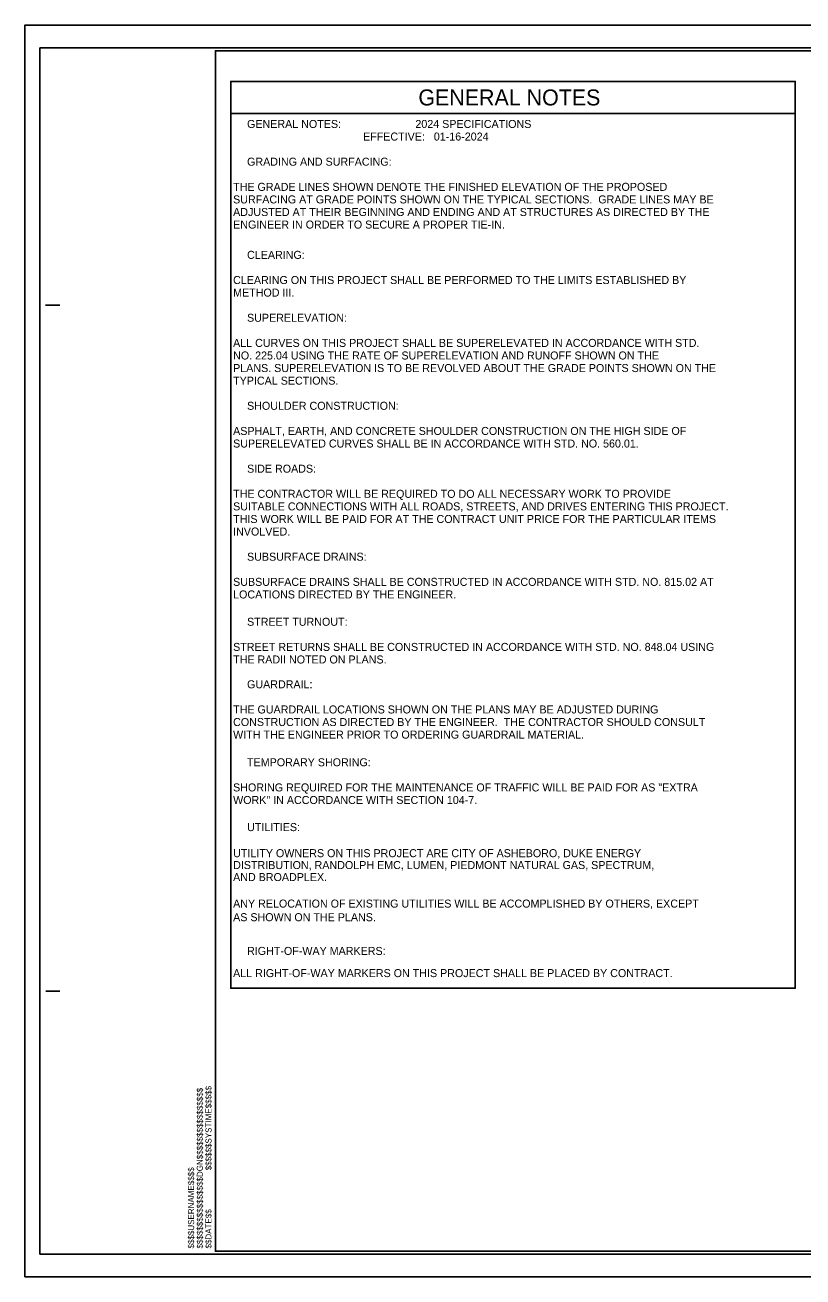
# Model space of a CAD drawing. Extents: x 1756641 to 5864777, y 736593 to 1246112.
# Drawn here: x 5863093 to 5863774, y 1245017 to 1246112 of the extents above; entities that cross this region are included whole.
import ezdxf

# ---------------------------------------------------------------- set-up
doc = ezdxf.new("R2010")
doc.units = 0
for name, color, linetype in [('Old_Level_14', 7, 'Continuous'), ('Old_Level_41', 7, 'Continuous'), ('Scratch_Level_1', 7, 'Continuous'), ('Sheet Cutting Line CELL', 7, 'Continuous'), ('Sheet Plan CELL', 7, 'Continuous'), ('Sheet Plot Border Inside CELL', 7, 'Continuous'), ('Sheet Plot Border Outside CELL', 7, 'Continuous')]:
    doc.layers.add(name, color=color, linetype=linetype)

msp = doc.modelspace()

# ---------------------------------------------------------------- linework, layer by layer
at = {"layer": 'Old_Level_14'}
msp.add_lwpolyline([(5863273.3, 1246034.2), (5863766.9, 1246034.2), (5863766.9, 1245269.1), (5863273.3, 1245269.1)], close=True, dxfattribs=at)
at = {"layer": 'Scratch_Level_1'}
msp.add_lwpolyline([(5863273.3, 1246034.2), (5863766.9, 1246034.2), (5863766.9, 1246062.2), (5863273.3, 1246062.2)], close=True, dxfattribs=at)
at = {"layer": 'Sheet Cutting Line CELL'}
for p, q in [((5864776.8, 1246111.5), (5863093.3, 1246111.5)), ((5863093.3, 1246111.5), (5863093.3, 1245016.5)), ((5863093.3, 1245016.5), (5864776.8, 1245016.5))]:
    msp.add_line(p, q, dxfattribs=at)
at = {"layer": 'Sheet Plan CELL'}
for p, q in [((5863259.8, 1246089), (5863259.8, 1246089)), ((5863111.3, 1245866.5), (5863123.8, 1245866.5)), ((5863111.4, 1245266.5), (5863123.9, 1245266.5)), ((5863259.8, 1245039), (5863259.8, 1245039))]:
    msp.add_line(p, q, dxfattribs=at)
for points in [[(5863259.8, 1245039), (5863259.8, 1246089), (5864559.8, 1246089.1), (5864559.8, 1245939), (5864759.8, 1245939), (5864759.8, 1245039)], [(5864759.9, 1246089), (5863259.8, 1246089), (5863259.8, 1245039), (5864759.8, 1245039)]]:
    msp.add_lwpolyline(points, close=True, dxfattribs=at)
at = {"layer": 'Sheet Plot Border Inside CELL'}
msp.add_lwpolyline([(5863106.3, 1245036.5), (5864772.3, 1245036.5), (5864772.3, 1246091.5), (5863106.3, 1246091.5)], close=True, dxfattribs=at)
at = {"layer": 'Sheet Plot Border Outside CELL'}
msp.add_lwpolyline([(5863093.3, 1245016.5), (5864776.8, 1245016.5), (5864776.8, 1246111.5), (5863093.3, 1246111.5)], close=True, dxfattribs=at)

# ---------------------------------------------------------------- texts
at = {"layer": 'Old_Level_14'}
for s, p in [('GENERAL NOTES:                         2024 SPECIFICATIONS', (5863287.5, 1246021.5)), ('                                       EFFECTIVE:   01-16-2024', (5863287.5, 1246010.5)), ('GRADING AND SURFACING:  ', (5863287.5, 1245988.5)), ('         THE GRADE LINES SHOWN DENOTE THE FINISHED ELEVATION OF THE PROPOSED ', (5863251.9, 1245966.5)), ('         SURFACING AT GRADE POINTS SHOWN ON THE TYPICAL SECTIONS.  GRADE LINES MAY BE ', (5863251.9, 1245955.5)), ('         ADJUSTED AT THEIR BEGINNING AND ENDING AND AT STRUCTURES AS DIRECTED BY THE', (5863251.9, 1245944.5)), ('         ENGINEER IN ORDER TO SECURE A PROPER TIE-IN.', (5863251.9, 1245933.5)), ('CLEARING:  ', (5863287.5, 1245907)), ('         CLEARING ON THIS PROJECT SHALL BE PERFORMED TO THE LIMITS ESTABLISHED BY ', (5863251.9, 1245885)), ('         METHOD III.', (5863251.9, 1245874)), ('SUPERELEVATION:  ', (5863287.5, 1245852)), ('         ALL CURVES ON THIS PROJECT SHALL BE SUPERELEVATED IN ACCORDANCE WITH STD. ', (5863251.9, 1245830)), ('         NO. 225.04 USING THE RATE OF SUPERELEVATION AND RUNOFF SHOWN ON THE', (5863251.9, 1245819)), ('         PLANS. SUPERELEVATION IS TO BE REVOLVED ABOUT THE GRADE POINTS SHOWN ON THE', (5863251.9, 1245808)), ('         TYPICAL SECTIONS.  ', (5863251.9, 1245797)), ('SHOULDER CONSTRUCTION:  ', (5863287.5, 1245775)), ('         ASPHALT, EARTH, AND CONCRETE SHOULDER CONSTRUCTION ON THE HIGH SIDE OF', (5863251.9, 1245753)), ('         SUPERELEVATED CURVES SHALL BE IN ACCORDANCE WITH STD. NO. 560.01.', (5863251.9, 1245742)), ('SIDE ROADS:', (5863287.5, 1245720)), ('         THE CONTRACTOR WILL BE REQUIRED TO DO ALL NECESSARY WORK TO PROVIDE ', (5863251.9, 1245698)), ('         SUITABLE CONNECTIONS WITH ALL ROADS, STREETS, AND DRIVES ENTERING THIS PROJECT.  ', (5863251.9, 1245687)), ('         THIS WORK WILL BE PAID FOR AT THE CONTRACT UNIT PRICE FOR THE PARTICULAR ITEMS ', (5863251.9, 1245676)), ('         INVOLVED.  ', (5863251.9, 1245665)), ('SUBSURFACE DRAINS:', (5863287.5, 1245643)), ('         SUBSURFACE DRAINS SHALL BE CONSTRUCTED IN ACCORDANCE WITH STD. NO. 815.02 AT ', (5863251.9, 1245621)), ('         LOCATIONS DIRECTED BY THE ENGINEER.  ', (5863251.9, 1245610)), ('STREET TURNOUT:  ', (5863287.5, 1245586.1)), ('         STREET RETURNS SHALL BE CONSTRUCTED IN ACCORDANCE WITH STD. NO. 848.04 USING', (5863251.9, 1245564.1)), ('         THE RADII NOTED ON PLANS.', (5863251.9, 1245553.1)), ('GUARDRAIL:  ', (5863287.5, 1245531.4)), ('         THE GUARDRAIL LOCATIONS SHOWN ON THE PLANS MAY BE ADJUSTED DURING ', (5863251.9, 1245509.4)), ('         CONSTRUCTION AS DIRECTED BY THE ENGINEER.  THE CONTRACTOR SHOULD CONSULT', (5863251.9, 1245498.4)), ('         WITH THE ENGINEER PRIOR TO ORDERING GUARDRAIL MATERIAL.', (5863251.9, 1245487.4)), ('TEMPORARY SHORING:', (5863287.5, 1245463.2)), ('         SHORING REQUIRED FOR THE MAINTENANCE OF TRAFFIC WILL BE PAID FOR AS "EXTRA', (5863251.9, 1245441.2)), ('         WORK" IN ACCORDANCE WITH SECTION 104-7.', (5863251.9, 1245430.2)), ('UTILITIES:  ', (5863287.5, 1245406.5)), ('         UTILITY OWNERS ON THIS PROJECT ARE CITY OF ASHEBORO, DUKE ENERGY ', (5863251.9, 1245383.7)), ('         DISTRIBUTION, RANDOLPH EMC, LUMEN, PIEDMONT NATURAL GAS, SPECTRUM,', (5863251.9, 1245373.3)), ('         AND BROADPLEX.', (5863251.9, 1245362.8)), ('         ANY RELOCATION OF EXISTING UTILITIES WILL BE ACCOMPLISHED BY OTHERS, EXCEPT ', (5863251.9, 1245339.6)), ('         AS SHOWN ON THE PLANS.  ', (5863251.9, 1245327.7)), ('RIGHT-OF-WAY MARKERS:  ', (5863287.5, 1245298.2)), ('         ALL RIGHT-OF-WAY MARKERS ON THIS PROJECT SHALL BE PLACED BY CONTRACT.', (5863251.9, 1245278.8))]:
    msp.add_text(s, height=7, dxfattribs=at).set_placement(p)
at = {"layer": 'Old_Level_41'}
for s, p in [('$$$$$$$$$$$$$$$$DGN$$$$$$$$$$$$$$$$', (5863248.8, 1245041.4)), ('$$$$$$SYSTIME$$$$$', (5863256.4, 1245109.8)), ('$$$$USERNAME$$$$', (5863241.2, 1245041.4)), ('$$DATE$$', (5863256.4, 1245041.4))]:
    msp.add_text(s, height=5.25, rotation=90, dxfattribs=at).set_placement(p)
at = {"layer": 'Scratch_Level_1'}
msp.add_text('GENERAL NOTES', height=14, dxfattribs=at).set_placement((5863437.3, 1246041.2))

doc.saveas('drawing.dxf')
